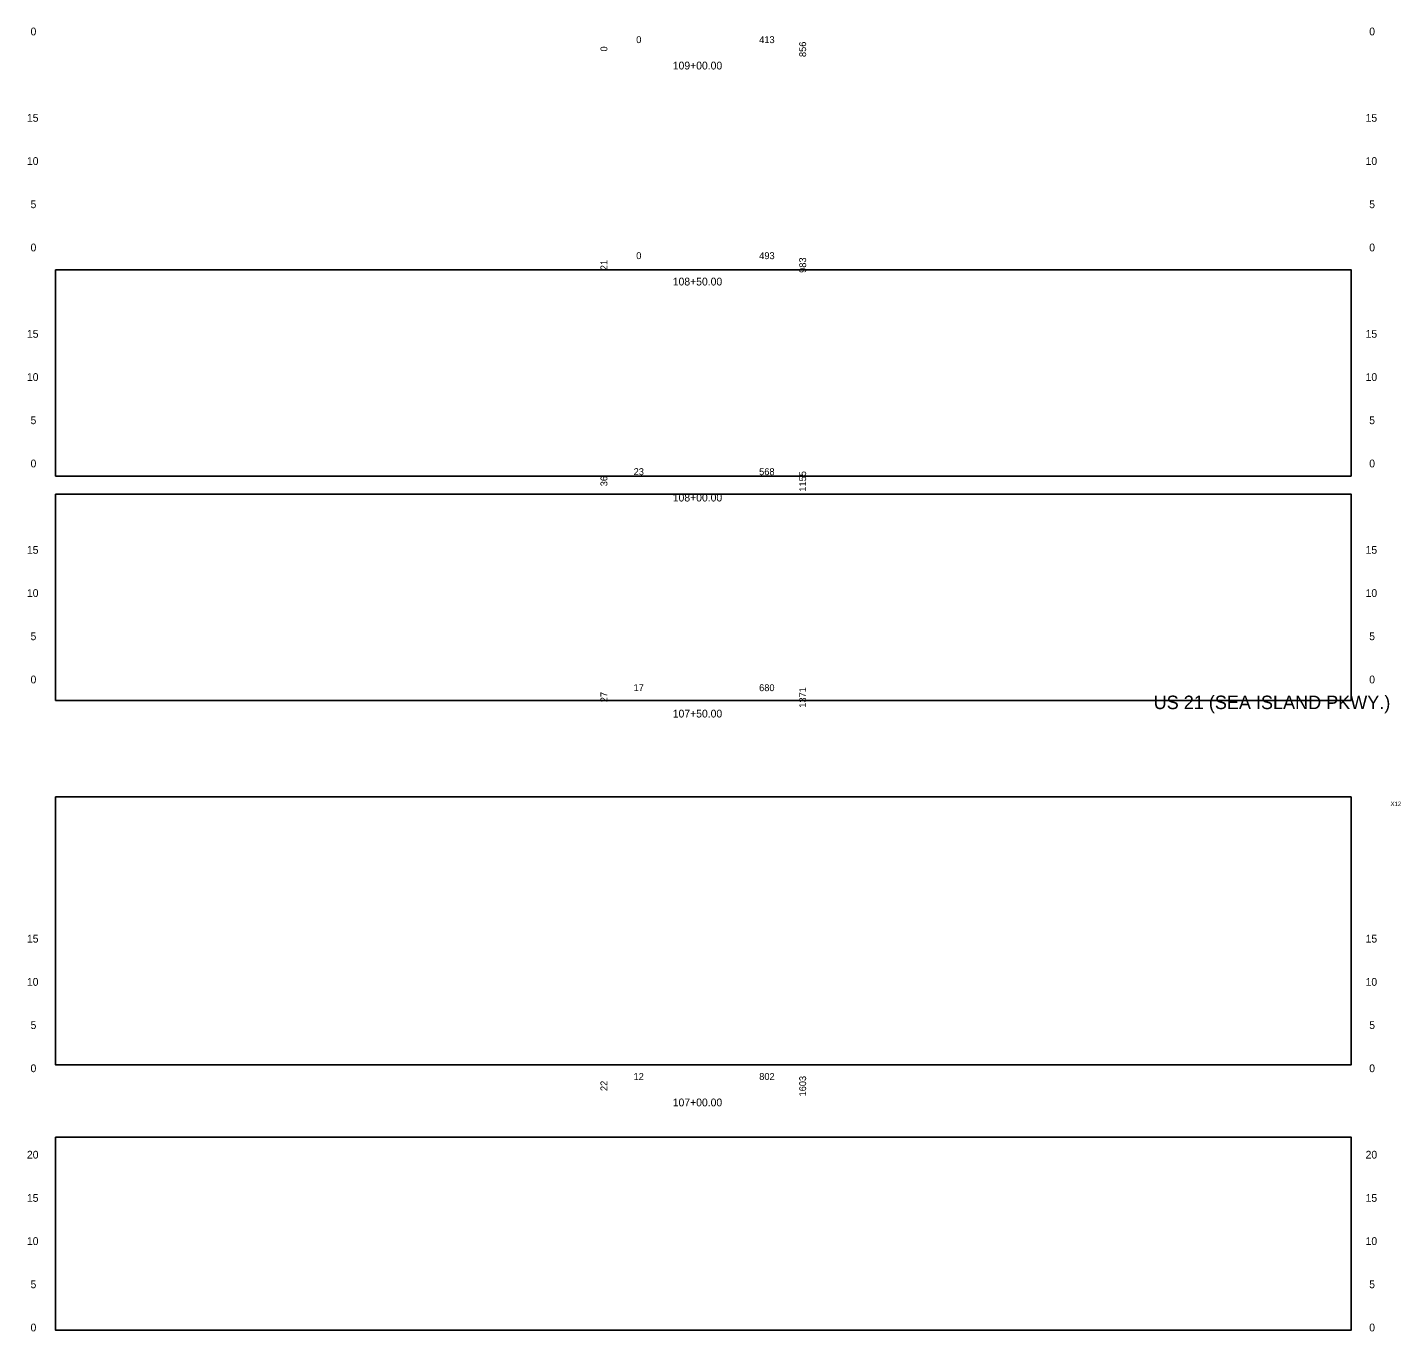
# Model space of a CAD drawing. Extents: x 971 to 1131, y 2203 to 6043.
# Drawn here: x 971.5 to 1130.5, y 4991.9 to 5142.8 of the extents above; entities that cross this region are included whole.
import ezdxf

# ---------------------------------------------------------------- set-up
doc = ezdxf.new("R2010")
doc.units = 0
for name, color, linetype in [('RD_SHT_Misc1', 7, 'Continuous'), ('RD_SHT_ShtClip', 7, 'Continuous'), ('RD_SHT_TX', 7, 'Continuous'), ('RD_XS_TX_Station', 7, 'Continuous')]:
    doc.layers.add(name, color=color, linetype=linetype)

msp = doc.modelspace()

# ---------------------------------------------------------------- linework, layer by layer
at = {"layer": 'RD_SHT_ShtClip'}
for points in [[(974.73, 5114.74), (1124.73, 5114.74), (1124.73, 5090.86), (974.73, 5090.86)], [(974.73, 5088.77), (1124.73, 5088.77), (1124.73, 5064.89), (974.73, 5064.89)], [(974.73, 5053.72), (1124.73, 5053.72), (1124.73, 5022.71), (974.73, 5022.71)], [(974.73, 5014.36), (1124.73, 5014.36), (1124.73, 4992), (974.73, 4992)]]:
    msp.add_lwpolyline(points, close=True, dxfattribs=at)

# ---------------------------------------------------------------- texts
at = {"layer": 'RD_SHT_Misc1'}
for s, rotation, p in [('0', 360, (1041.97, 5140.97)), ('413', 360, (1056.21, 5140.97)), ('0', 90, (1038.63, 5140)), ('856', 90, (1061.64, 5139.36)), ('0', 360, (1041.97, 5115.97)), ('983', 90, (1061.64, 5114.38)), ('21', 90, (1038.63, 5114.69)), ('36', 90, (1038.63, 5089.68)), ('1155', 90, (1061.64, 5089.06)), ('27', 90, (1038.63, 5064.69)), ('1371', 90, (1061.64, 5064.05)), ('22', 90, (1038.63, 5019.69)), ('1603', 90, (1061.64, 5019.06))]:
    msp.add_text(s, height=0.8, rotation=rotation, dxfattribs=at).set_placement(p)
for s, p in [('493', (1056.21, 5115.97)), ('23', (1041.67, 5090.97)), ('568', (1056.2, 5090.97)), ('680', (1056.2, 5065.97)), ('17', (1041.66, 5065.97)), ('12', (1041.66, 5020.97)), ('802', (1056.21, 5020.97))]:
    msp.add_text(s, height=0.8, dxfattribs=at).set_placement(p)
at = {"layer": 'RD_SHT_TX'}
for s, height, p in [('0', 0.9, (971.84, 5141.87)), ('0', 0.9, (1126.84, 5141.87)), ('15', 0.9, (971.42, 5131.87)), ('15', 0.9, (1126.42, 5131.87)), ('10', 0.9, (971.42, 5126.87)), ('10', 0.9, (1126.42, 5126.87)), ('5', 0.9, (971.84, 5121.87)), ('5', 0.9, (1126.84, 5121.87)), ('0', 0.9, (971.84, 5116.87)), ('0', 0.9, (1126.84, 5116.87)), ('15', 0.9, (971.42, 5106.87)), ('15', 0.9, (1126.42, 5106.87)), ('10', 0.9, (971.42, 5101.87)), ('10', 0.9, (1126.42, 5101.87)), ('5', 0.9, (971.84, 5096.87)), ('5', 0.9, (1126.84, 5096.87)), ('0', 0.9, (971.84, 5091.87)), ('0', 0.9, (1126.84, 5091.87)), ('15', 0.9, (971.42, 5081.87)), ('15', 0.9, (1126.42, 5081.87)), ('10', 0.9, (971.42, 5076.87)), ('10', 0.9, (1126.42, 5076.87)), ('5', 0.9, (971.84, 5071.87)), ('5', 0.9, (1126.84, 5071.87)), ('0', 0.9, (971.84, 5066.87)), ('0', 0.9, (1126.84, 5066.87)), ('US 21 (SEA ISLAND PKWY.)', 1.5625, (1101.88, 5063.89)), ('15', 0.9, (971.42, 5036.87)), ('15', 0.9, (1126.42, 5036.87)), ('10', 0.9, (971.42, 5031.87)), ('10', 0.9, (1126.42, 5031.87)), ('5', 0.9, (971.84, 5026.87)), ('5', 0.9, (1126.84, 5026.87)), ('0', 0.9, (971.84, 5021.87)), ('0', 0.9, (1126.84, 5021.87)), ('20', 0.9, (971.42, 5011.87)), ('20', 0.9, (1126.42, 5011.87)), ('15', 0.9, (971.42, 5006.87)), ('15', 0.9, (1126.42, 5006.87)), ('10', 0.9, (971.42, 5001.87)), ('10', 0.9, (1126.42, 5001.87)), ('5', 0.9, (971.84, 4996.87)), ('5', 0.9, (1126.84, 4996.87)), ('0', 0.9, (971.84, 4991.87)), ('0', 0.9, (1126.84, 4991.87))]:
    msp.add_text(s, height=height, dxfattribs=at).set_placement(p)
msp.add_text('X12', height=0.5, rotation=360, dxfattribs=at).set_placement((1129.31, 5052.68))
at = {"layer": 'RD_XS_TX_Station'}
for s, p in [('109+00.00', (1046.2, 5137.92)), ('108+50.00', (1046.2, 5112.92)), ('108+00.00', (1046.2, 5087.92)), ('107+50.00', (1046.2, 5062.92)), ('107+00.00', (1046.2, 5017.92))]:
    msp.add_text(s, height=0.9, dxfattribs=at).set_placement(p)

doc.saveas('drawing.dxf')
